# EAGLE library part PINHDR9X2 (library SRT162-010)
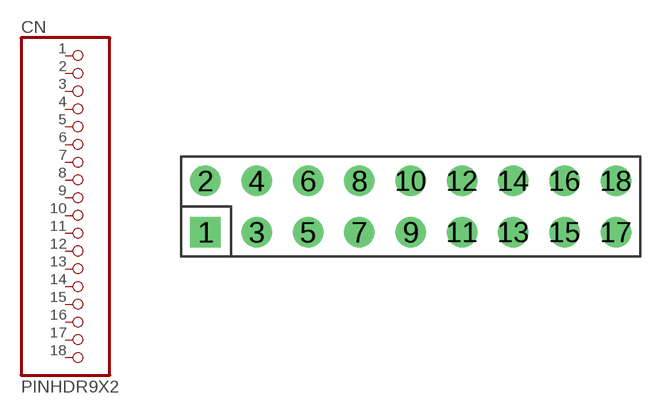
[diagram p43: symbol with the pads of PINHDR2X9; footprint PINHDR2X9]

Designator prefix CN

## PINHDR9X2  [PINHDR2X9]
1  1  pas
2  2  pas
3  3  pas
4  4  pas
5  5  pas
6  6  pas
7  7  pas
8  8  pas
9  9  pas
10  10  pas
11  11  pas
12  12  pas
13  13  pas
14  14  pas
15  15  pas
16  16  pas
17  17  pas
18  18  pas

## Footprint PINHDR2X9 (pad centres in mm)
drill 1 square: 1 -10.16,-1.27
drill 1 round: 2 -10.16,1.27; 3 -7.62,-1.27; 4 -7.62,1.27; 5 -5.08,-1.27; 6 -5.08,1.27; 7 -2.54,-1.27; 8 -2.54,1.27; 9 0,-1.27; 10 0,1.27; 11 2.54,-1.27; 12 2.54,1.27; 13 5.08,-1.27; 14 5.08,1.27; 15 7.62,-1.27; 16 7.62,1.27; 17 10.16,-1.27; 18 10.16,1.27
